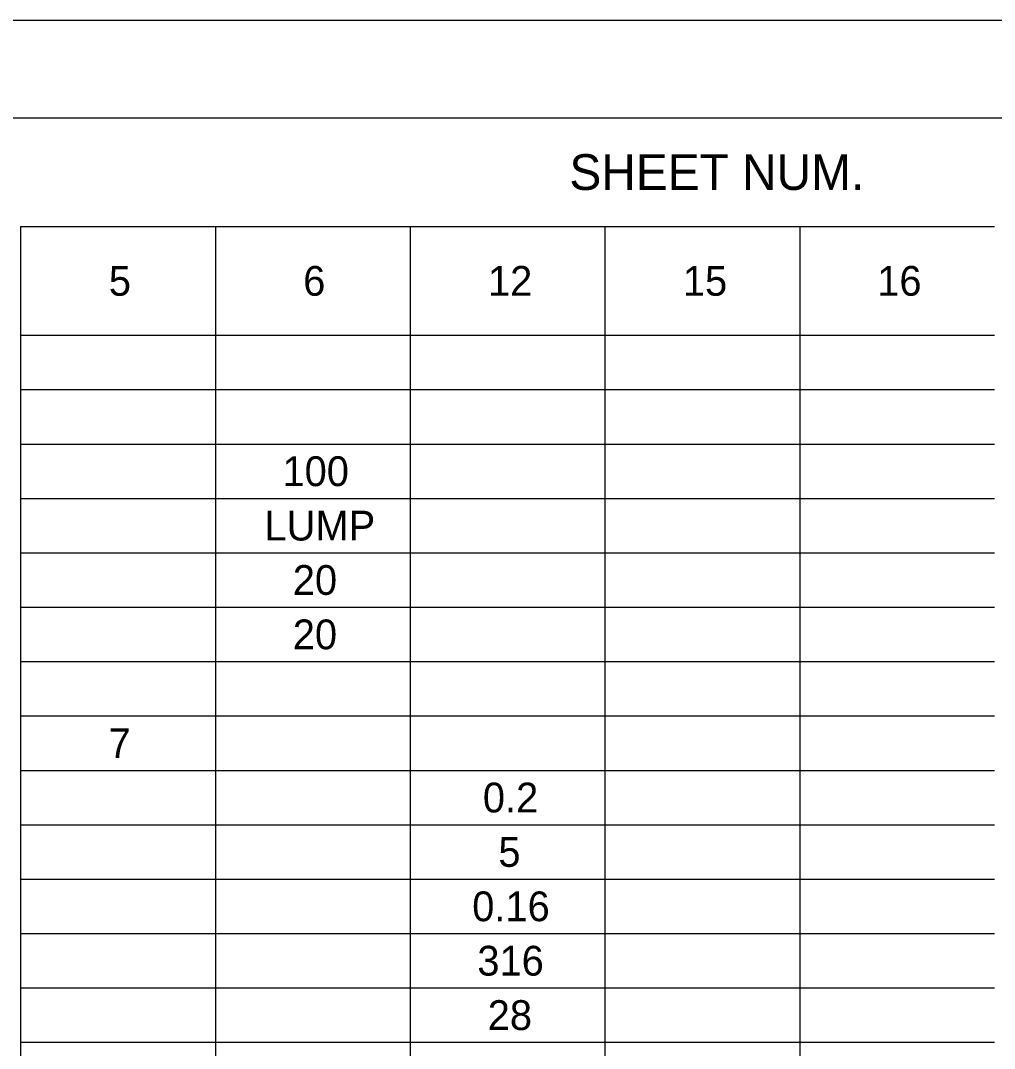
# Model space of a CAD drawing. Extents: x 0 to 34, y 0 to 22.
# Drawn here: x 3.51 to 8.52, y 16.71 to 22 of the extents above; entities that cross this region are included whole.
import ezdxf

# ---------------------------------------------------------------- set-up
doc = ezdxf.new("R2010")
doc.units = 0
for name, color, linetype in [('SH_Border', 7, 'Continuous'), ('SH_Cut_Line', 7, 'Continuous'), ('SH_Text', 7, 'Continuous')]:
    doc.layers.add(name, color=color, linetype=linetype)

msp = doc.modelspace()

# ---------------------------------------------------------------- linework, layer by layer
at = {"layer": 'SH_Border'}
msp.add_lwpolyline([(1.5, 21.5), (33.5, 21.5), (33.5, 0.5), (1.5, 0.5)], close=True, dxfattribs=at)
at = {"layer": 'SH_Cut_Line'}
msp.add_lwpolyline([(0, 0), (34, 0), (34, 22), (0, 22)], close=True, dxfattribs=at)
at = {"layer": 'SH_Text'}
for p, q in [((3.5051, 21.5), (4.5076, 21.5)), ((4.5076, 21.5), (5.5101, 21.5)), ((5.5101, 21.5), (6.5126, 21.5)), ((6.5126, 21.5), (7.5152, 21.5)), ((7.5152, 21.5), (8.5177, 21.5)), ((3.5051, 20.94), (4.5076, 20.94)), ((3.5051, 20.94), (3.5051, 20.66)), ((4.5076, 20.94), (5.5101, 20.94)), ((4.5076, 20.94), (4.5076, 20.66)), ((5.5101, 20.94), (6.5126, 20.94)), ((5.5101, 20.94), (5.5101, 20.66)), ((6.5126, 20.94), (7.5152, 20.94)), ((6.5126, 20.94), (6.5126, 20.66)), ((7.5152, 20.94), (8.5177, 20.94)), ((7.5152, 20.94), (7.5152, 20.66)), ((3.5051, 20.66), (3.5051, 20.38)), ((4.5076, 20.66), (4.5076, 20.38)), ((5.5101, 20.66), (5.5101, 20.38)), ((6.5126, 20.66), (6.5126, 20.38)), ((7.5152, 20.66), (7.5152, 20.38)), ((3.5051, 20.38), (4.5076, 20.38)), ((3.5051, 20.38), (3.5051, 20.1)), ((4.5076, 20.38), (5.5101, 20.38)), ((4.5076, 20.38), (4.5076, 20.1)), ((5.5101, 20.38), (6.5126, 20.38)), ((5.5101, 20.38), (5.5101, 20.1)), ((6.5126, 20.38), (7.5152, 20.38)), ((6.5126, 20.38), (6.5126, 20.1)), ((7.5152, 20.38), (8.5177, 20.38)), ((7.5152, 20.38), (7.5152, 20.1)), ((3.5051, 20.1), (4.5076, 20.1)), ((3.5051, 20.1), (3.5051, 18.7)), ((4.5076, 20.1), (5.5101, 20.1)), ((4.5076, 20.1), (4.5076, 18.7)), ((5.5101, 20.1), (6.5126, 20.1)), ((5.5101, 20.1), (5.5101, 18.7)), ((6.5126, 20.1), (7.5152, 20.1)), ((6.5126, 20.1), (6.5126, 18.7)), ((7.5152, 20.1), (8.5177, 20.1)), ((7.5152, 20.1), (7.5152, 18.7)), ((3.5051, 19.82), (4.5076, 19.82)), ((4.5076, 19.82), (5.5101, 19.82)), ((5.5101, 19.82), (6.5126, 19.82)), ((6.5126, 19.82), (7.5152, 19.82)), ((7.5152, 19.82), (8.5177, 19.82)), ((3.5051, 19.54), (4.5076, 19.54)), ((4.5076, 19.54), (5.5101, 19.54)), ((5.5101, 19.54), (6.5126, 19.54)), ((6.5126, 19.54), (7.5152, 19.54)), ((7.5152, 19.54), (8.5177, 19.54)), ((3.5051, 19.26), (4.5076, 19.26)), ((4.5076, 19.26), (5.5101, 19.26)), ((5.5101, 19.26), (6.5126, 19.26)), ((6.5126, 19.26), (7.5152, 19.26)), ((7.5152, 19.26), (8.5177, 19.26)), ((3.5051, 18.98), (4.5076, 18.98)), ((4.5076, 18.98), (5.5101, 18.98)), ((5.5101, 18.98), (6.5126, 18.98)), ((6.5126, 18.98), (7.5152, 18.98)), ((7.5152, 18.98), (8.5177, 18.98)), ((3.5051, 18.7), (4.5076, 18.7)), ((3.5051, 18.7), (3.5051, 18.14)), ((4.5076, 18.7), (5.5101, 18.7)), ((4.5076, 18.7), (4.5076, 18.14)), ((5.5101, 18.7), (6.5126, 18.7)), ((5.5101, 18.7), (5.5101, 18.14)), ((6.5126, 18.7), (7.5152, 18.7)), ((6.5126, 18.7), (6.5126, 18.14)), ((7.5152, 18.7), (8.5177, 18.7)), ((7.5152, 18.7), (7.5152, 18.14)), ((3.5051, 18.42), (4.5076, 18.42)), ((4.5076, 18.42), (5.5101, 18.42)), ((5.5101, 18.42), (6.5126, 18.42)), ((6.5126, 18.42), (7.5152, 18.42)), ((7.5152, 18.42), (8.5177, 18.42)), ((3.5051, 18.14), (4.5076, 18.14)), ((3.5051, 18.14), (3.5051, 17.86)), ((4.5076, 18.14), (5.5101, 18.14)), ((4.5076, 18.14), (4.5076, 17.86)), ((5.5101, 18.14), (6.5126, 18.14)), ((5.5101, 18.14), (5.5101, 17.86)), ((6.5126, 18.14), (7.5152, 18.14)), ((6.5126, 18.14), (6.5126, 17.86)), ((7.5152, 18.14), (8.5177, 18.14)), ((7.5152, 18.14), (7.5152, 17.86)), ((3.5051, 17.86), (4.5076, 17.86)), ((3.5051, 17.86), (3.5051, 17.58)), ((4.5076, 17.86), (5.5101, 17.86)), ((4.5076, 17.86), (4.5076, 17.58)), ((5.5101, 17.86), (6.5126, 17.86)), ((5.5101, 17.86), (5.5101, 17.58)), ((6.5126, 17.86), (7.5152, 17.86)), ((6.5126, 17.86), (6.5126, 17.58)), ((7.5152, 17.86), (8.5177, 17.86)), ((7.5152, 17.86), (7.5152, 17.58)), ((3.5051, 17.58), (4.5076, 17.58)), ((3.5051, 17.58), (3.5051, 17.3)), ((4.5076, 17.58), (5.5101, 17.58)), ((4.5076, 17.58), (4.5076, 17.3)), ((5.5101, 17.58), (6.5126, 17.58)), ((5.5101, 17.58), (5.5101, 17.3)), ((6.5126, 17.58), (7.5152, 17.58)), ((6.5126, 17.58), (6.5126, 17.3)), ((7.5152, 17.58), (8.5177, 17.58)), ((7.5152, 17.58), (7.5152, 17.3)), ((3.5051, 17.3), (4.5076, 17.3)), ((3.5051, 17.3), (3.5051, 17.02)), ((4.5076, 17.3), (5.5101, 17.3)), ((4.5076, 17.3), (4.5076, 17.02)), ((5.5101, 17.3), (6.5126, 17.3)), ((5.5101, 17.3), (5.5101, 17.02)), ((6.5126, 17.3), (7.5152, 17.3)), ((6.5126, 17.3), (6.5126, 17.02)), ((7.5152, 17.3), (8.5177, 17.3)), ((7.5152, 17.3), (7.5152, 17.02)), ((3.5051, 17.02), (4.5076, 17.02)), ((3.5051, 17.02), (3.5051, 16.74)), ((4.5076, 17.02), (5.5101, 17.02)), ((4.5076, 17.02), (4.5076, 16.74)), ((5.5101, 17.02), (6.5126, 17.02)), ((5.5101, 17.02), (5.5101, 16.74)), ((6.5126, 17.02), (7.5152, 17.02)), ((6.5126, 17.02), (6.5126, 16.74)), ((7.5152, 17.02), (8.5177, 17.02)), ((7.5152, 17.02), (7.5152, 16.74)), ((3.5051, 16.74), (4.5076, 16.74)), ((3.5051, 16.74), (3.5051, 16.18)), ((4.5076, 16.74), (5.5101, 16.74)), ((4.5076, 16.74), (4.5076, 16.18)), ((5.5101, 16.74), (6.5126, 16.74)), ((5.5101, 16.74), (5.5101, 16.18)), ((6.5126, 16.74), (7.5152, 16.74)), ((6.5126, 16.74), (6.5126, 16.18)), ((7.5152, 16.74), (8.5177, 16.74)), ((7.5152, 16.74), (7.5152, 16.18))]:
    msp.add_line(p, q, dxfattribs=at)

# ---------------------------------------------------------------- texts
for s, height, p in [('SHEET NUM.', 0.184, (6.33, 21.128)), ('5', 0.1533, (3.9594, 20.5833)), ('6', 0.1533, (4.9599, 20.5833)), ('12', 0.15333, (5.911, 20.5833)), ('15', 0.15333, (6.9139, 20.5833)), ('16', 0.15333, (7.9144, 20.5833)), ('100', 0.15333, (4.8532, 19.6033)), ('LUMP', 0.15333, (4.7607, 19.3233)), ('20', 0.15333, (4.9063, 19.0433)), ('20', 0.15333, (4.9063, 18.7633)), ('7', 0.1533, (3.958, 18.2033)), ('0.2', 0.15333, (5.8845, 17.9233)), ('5', 0.1533, (5.9644, 17.6433)), ('0.16', 0.15333, (5.8298, 17.3633)), ('316', 0.15333, (5.8562, 17.0833)), ('28', 0.15333, (5.9095, 16.8033))]:
    msp.add_text(s, height=height, dxfattribs=at).set_placement(p)

doc.saveas('drawing.dxf')
